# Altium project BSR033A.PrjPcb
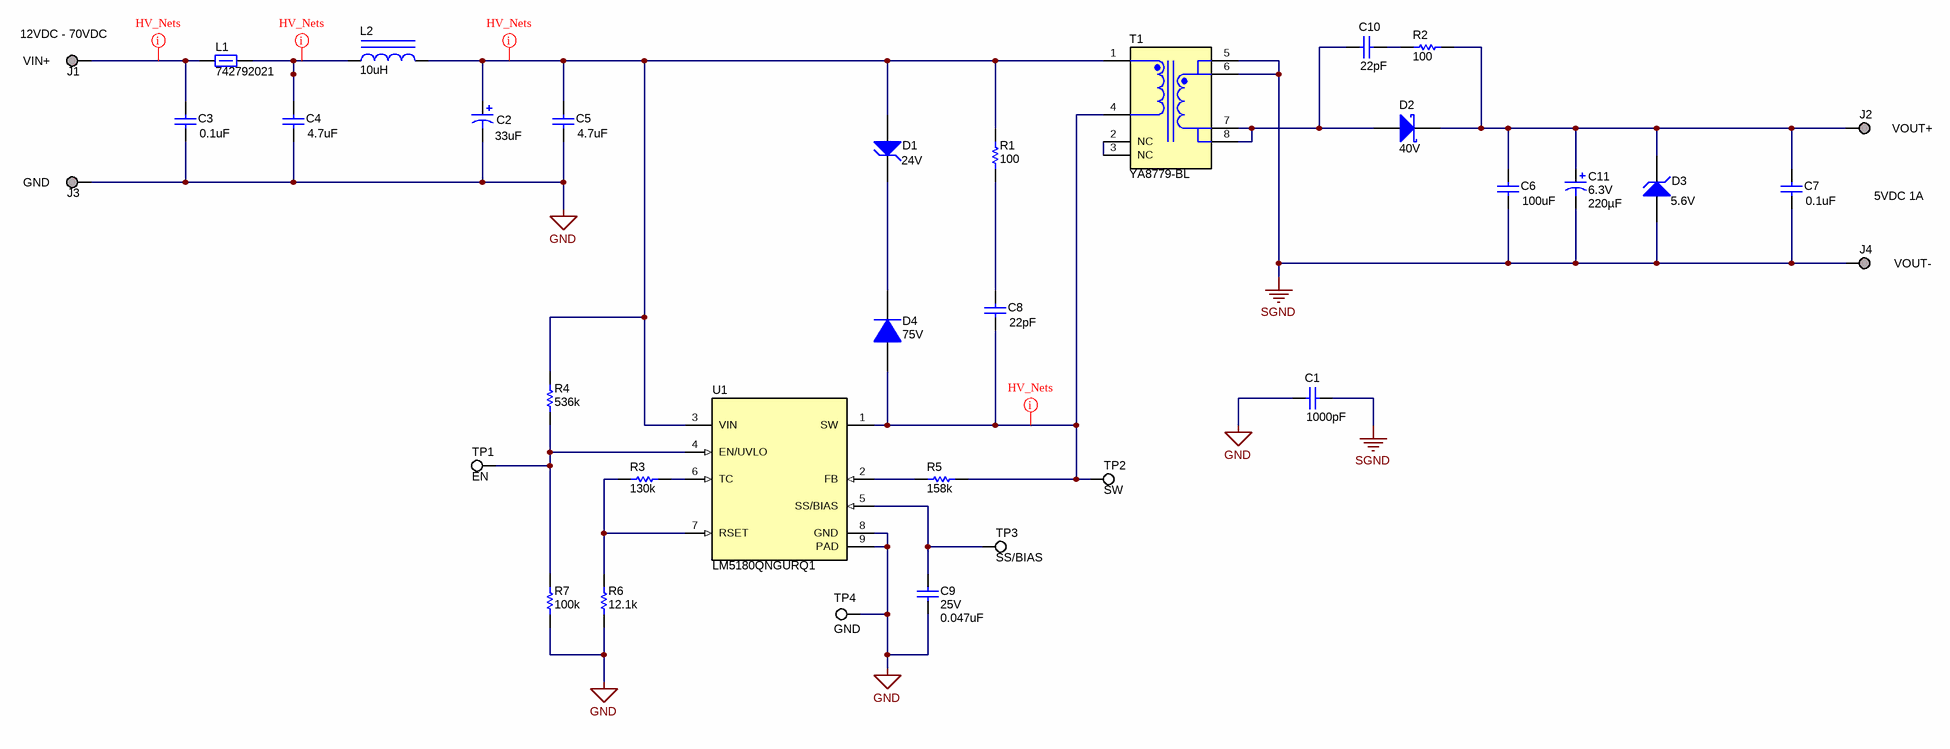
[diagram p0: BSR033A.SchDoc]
CopyrightYear: 2017; PCB_Layout: K Nielson; PCB_Rev: A; PRJ_Customer: Public Release; PRJ_Engineer: T Hegarty; PRJ_Number: BSR033; PRJ_Title: LM5180EVM-S05; SCH_Rev: A; TechSupport: http://www.ti.com/support; TID: N/A; VIN_Config: 18VDC - 70VDC; VOUT_ADC: 1A; VOUT_VDC: 5VDC
2 sheets, 53 parts. Net scope: global (net labels, ports and power ports of the same name join across sheets).
Board file: BSR033A.PcbDoc
Sheets:
  BSR033A.SchDoc
  BSR033A_Hardware.SchDoc

## Sheet BSR033A.SchDoc: LM5180EVM-S05 Buck Converter Schematic
size 431 x 279 mm; Date: Not shown in title block; ApprovedBy: Not shown in title block; CheckedBy: Not shown in title block; Author: Not shown in title block; CompanyName: Not shown in title block; DrawnBy: K Nielson; Engineer: Not shown in title block; Organization: Not shown in title block; Address1: Not shown in title block; Address2: Not shown in title block; Address3: Not shown in title block; Address4: Not shown in title block; DocumentNumber: 1; Revision: Use project parameter SCH_Rev; SheetNumber: 1; SheetTotal: 2; PageSetup: Record=PageOptions¦CenterHorizontal=True¦CenterVertical=True¦PrintScale=1.00¦XCorrection=1.00¦YCorrection=1.00¦PrintKind=0¦BorderSize=5000000¦LeftOffset=0¦BottomOffset=0¦Orientation=2¦PaperLength=1000¦PaperWidth=1000¦Scale=100¦PaperSource=15¦PrintQuality=600¦MediaType=1¦DitherType=10¦PaperKind=Letter¦PrintScaleMode=1

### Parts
C1  ValueDisplayed: 1000pF  [1206_190]  (hidden comment: 202R18W102KV4E)
C2  ValueDisplayed: 33uF  [SM_RADIAL_G]  (hidden comment: EEE-FK2A330P)
C3  ValueDisplayed: 0.1uF  [0603L]  (hidden comment: GRM188R72A104KA35J)
C4  ValueDisplayed: 4.7uF  [1210_220]  (hidden comment: GRM32DC72A475KE01L)
C5  ValueDisplayed: 4.7uF  [1210_220]  (hidden comment: GRM32DC72A475KE01L)
C6  ValueDisplayed: 100uF  [1210_270]  (hidden comment: GRM32EC80J107ME20L)
C7  ValueDisplayed: 0.1uF  [0603L]  (hidden comment: GRM188R72A104KA35J)
C8  ValueDisplayed: 22pF  [0603_HV]  (hidden comment: GRM1885C2A220JA01D)
C9  VDC_V: 25V  ValueDisplayed: 0.047uF  [0603L]  (hidden comment: GCM188R71E473KA37D)
C10  ValueDisplayed: 22pF  [0603_HV]  (hidden comment: GRM1885C2A220JA01D)
C11  VDC_V: 6.3V  ValueDisplayed: 220µF  [7343-31]  (hidden comment: T598D107M010ATE025)
D1  Vz_V: 24V  [PowerDI123]  (hidden comment: DFLZ24-7)
D2  40V  [SMAF]
D3  Vz_V: 5.6V  [SOD-323]  (hidden comment: MMSZ5232BS-7-F)
D4  75V  [SOD-323]
J1  1573-2  [Keystone1573-2]  (value not drawn)
J2  1573-2  [Keystone1573-2]  (value not drawn)
J3  1573-2  [Keystone1573-2]  (value not drawn)
J4  1573-2  [Keystone1573-2]  (value not drawn)
L1  742792021  [0805_HV]
L2  ValueDisplayed: 10uH  [WE-TPC-M1]  (hidden comment: 744042100)
R1  ValueDisplayed: 100  [0603L]  (hidden comment: CRCW0603100RFKEA)
R2  ValueDisplayed: 100  [0603L]  (hidden comment: CRCW0603100RFKEA)
R3  ValueDisplayed: 130k  [0603L]  (hidden comment: CRCW0603130KFKEA)
R4  ValueDisplayed: 536k  [0603_HV]  (hidden comment: CRCW0603536KFKEA)
R5  ValueDisplayed: 158k  [0603_HV]  (hidden comment: CRCW0603158KFKEA)
R6  ValueDisplayed: 12.1k  [0603L]  (hidden comment: CRCW060312K1FKEA)
R7  ValueDisplayed: 100k  [0603L]  (hidden comment: CRCW0603100KFKEA)
T1  YA8779-BL  [Coilcraft_YA8779-CL]
TP1  EN  [Testpoint_Keystone_Miniature]
TP2  SW  [Testpoint_Keystone_Miniature]
TP3  SS/BIAS  [Testpoint_Keystone_Miniature]
TP4  GND  [Testpoint_Keystone_Miniature]
U1  LM5180QNGURQ1  [NGU0008C]

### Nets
GND: C1.2 C2.2(-) C3.2 C4.1 C5.1 C9.2 J3.1 R6.1 R7.1 TP4.1 U1.8(GND) U1.9(PAD)
SGND: C1.1 C6.2 C7.2 C11.2(-) D3.2(A) J4.1 T1.5 T1.6
NetC2_1: C2.1(+) C5.2 D1.2(A) L2.2 R1.2 R4.2 T1.1 U1.3(VIN)
NetC3_1: C3.1 J1.1 L1.1
NetC4_2: C4.2 L1.2 L2.1
NetC6_1: C6.1 C7.1 C11.1(+) D2.1(K) D3.1(K) J2.1 R2.1
NetC8_1: C8.1 R1.1
NetC8_2: C8.2 D4.2(A) R5.2 T1.4 TP2.1 U1.1(SW)
NetC9_1: C9.1 TP3.1 U1.5(SS/BIAS)
NetC10_1: C10.1 R2.2
NetC10_2: C10.2 D2.2(A) T1.7 T1.8
NetD1_1: D1.1(K) D4.1(K)
NetR3_1: R3.1 R6.2 U1.7(RSET)
NetR3_2: R3.2 U1.6(TC)
NetR4_1: R4.1 R7.2 TP1.1 U1.4(EN/UVLO)
NetR5_1: R5.1 U1.2(FB)
NetT1_2: T1.2(NC) T1.3(NC)

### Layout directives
net class HV_Nets: NetC2_1, NetC3_1, NetC4_2, NetC8_2

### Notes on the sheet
- (near J1) 12VDC - 70VDC
- (near J1) VIN+
- (near J3) GND
- (near J2) VOUT+
- 5VDC 1A
- (near J4) VOUT-

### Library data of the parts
C1 = CMP-0008572-2: CAP, CERM, 1000 pF, 2000 V, +/- 10%, X7R, 1206_190; Manufacturer: Johanson Technology; TaMin_C: -55°C; Polarized: N; SizeAreaWB_mm2: 10.92; Value1: Unknown; U/M: EA; Value: 1000pF; TaMax_C: 125°C; SizeZ_mm: 1.9; SizeX_mm: 3.2; SizeY_mm: 1.6; Cap_Case: 1206; Value2: 2000V; SizeArea_mm2: 5.12; CompType: Capacitor; Cap_F: 1nF; VDC_V: 2kV; AEC Category: Q200
C2 = CMP-0011203-2: CAP, AL, 33 uF, 100 V, +/- 20%, 0.7 ohm, AEC-Q200 Grade 2, SMD; Manufacturer: Panasonic; TaMin_C: -55°C; Polarized: Y; SizeAreaWB_mm2: 172.2; Value1: 0.7 ohm; U/M: EA; Value: 33uF; TaMax_C: 105°C; SizeZ_mm: 10.2; SizeX_mm: 12; SizeY_mm: 10.3; Cap_Case: G; Value2: 100V; SizeArea_mm2: 123.6; CompType: Capacitor; Cap_F: 33µF; IRMS_A: 2dA; AEC Grade: 2; AEC Category: Q200; ESR_ohm: 7d
C3 C7 = CMP-0007470-5: CAP, CERM, 0.1 uF, 100 V, +/- 10%, X7R, 0603; Manufacturer: MuRata; TaMin_C: -55°C; Polarized: N; SizeAreaWB_mm2: 4.68; Value1: Unknown; U/M: EA; Value: 0.1uF; TaMax_C: 125°C; SizeZ_mm: 1; SizeX_mm: 1.6; SizeY_mm: 0.8; Cap_Case: 0603; Value2: 100V; SizeArea_mm2: 1.28; CompType: Capacitor; Cap_F: 100nF; AEC Category: Q200
C4 C5 = CMP-0009182-2: CAP, CERM, 4.7 uF, 100 V, +/- 10%, X7S, 1210; Manufacturer: MuRata; TaMin_C: -55°C; Polarized: N; SizeAreaWB_mm2: 14.7; Value1: Unknown; U/M: EA; Value: 4.7uF; TaMax_C: 125°C; SizeZ_mm: 2.2; SizeX_mm: 3.2; SizeY_mm: 2.5; Cap_Case: 1210; Value2: 100V; SizeArea_mm2: 8; CompType: Capacitor; Cap_F: 4.7µF; AEC Category: Q200
C6 = CMP-0009199-2: CAP, CERM, 100 uF, 6.3 V, +/- 20%, X6S, 1210; Manufacturer: MuRata; TaMin_C: -55°C; Polarized: N; SizeAreaWB_mm2: 14.7; Value1: Unknown; U/M: EA; Value: 100uF; TaMax_C: 105°C; SizeZ_mm: 2.7; SizeX_mm: 3.2; SizeY_mm: 2.5; Cap_Case: 1210; Value2: 6.3V; SizeArea_mm2: 8; Cap_F: 100µF; AEC Category: Q200
C8 = CMP-0007255-4: CAP, CERM, 22 pF, 100 V, +/- 5%, C0G/NP0, 0603; Manufacturer: MuRata; TaMin_C: -55°C; Polarized: N; SizeAreaWB_mm2: 4.68; Value1: Unknown; U/M: EA; Value: 22pF; TaMax_C: 125°C; SizeZ_mm: 1; SizeX_mm: 1.6; SizeY_mm: 0.8; Cap_Case: 0603; Value2: 100V; SizeArea_mm2: 1.28; CompType: Capacitor; AEC Category: Q200
C9 = CMP-0007141-5: CAP, CERM, 0.047 uF, 25 V, +/- 10%, X7R, AEC-Q200 Grade 1, 0603; Manufacturer: MuRata; TaMin_C: -55°C; Polarized: N; SizeAreaWB_mm2: 4.68; Value1: Unknown; U/M: EA; TaMax_C: 125°C; SizeZ_mm: 1; SizeX_mm: 1.6; SizeY_mm: 0.8; Cap_Case: 0603; SizeArea_mm2: 1.28; CompType: Capacitor; AEC Qualified: Y; Cap_F: 47nF; AEC Category: Q200
C10 = CMP-0007255-4: CAP, CERM, 22 pF, 100 V, +/- 5%, C0G/NP0, 0603; Manufacturer: MuRata; TaMin_C: -55°C; Polarized: N; SizeAreaWB_mm2: 4.68; U/M: EA; Value: 22pF; TaMax_C: 125°C; SizeZ_mm: 1; SizeX_mm: 1.6; SizeY_mm: 0.8; Cap_Case: 0603; Value2: 100V; SizeArea_mm2: 1.28; CompType: Capacitor; AEC Category: Q200; Value1: Unknown
C11 = CMP-0074683-2: CAP, Aluminum Polymer, 220 µF, 6.3 V,+/- 20%, 0.01 ohm, 7343-31 SMD; Manufacturer: MuRata; PartNumber: ECASD60J227M010K00; TaMin_C: -40°C; ESR_ohm: 0.01; Polarized: Y; SizeAreaWB_mm2: 58.59; Value: 220uF; TaMax_C: 105°C; SizeZ_mm: 3.1; SizeX_mm: 7.3; SizeY_mm: 4.3; SizeArea_mm2: 31.39; CompType: Capacitor; AEC Qualified: N; IRMS_A: 3A; AEC Category: Q200
D1 = CMP-0005415-2: Diode, Zener, 24 V, 1 W, PowerDI123; Manufacturer: Diodes Inc.; Power_W: 1W; SizeAreaWB_mm2: 13.066; RJA_CperW: 110; U/M: EA; Value: 24V; SizeZ_mm: 0.98; SizeX_mm: 3.7; SizeY_mm: 1.78; SizeArea_mm2: 6.586; AEC Category: Q101
D2 = CMP-0028855-1: Diode, Schottky, 40 V, 3 A, AEC-Q101, SMAF; PartNumber: FSV340AF; Manufacturer: Fairchild Semiconductor; SizeAreaWB_mm2: 19.95; SizeArea_mm2: 11.75; AEC Qualified: Y; TJmax_C: 150°C; AEC Category: Q101; SizeZ_mm: 1; Green_REACh: Incomplete; Io_A: 3A; Vf_V: 5dV; SizeY_mm: 2.5; Value2: 0.5V; Green_Lifecycle: Not Set; U/M: EA; SizeX_mm: 4.7
D3 = CMP-0005855-1: Diode, Zener, 5.6 V, 200 mW, SOD-323; Manufacturer: Diodes Inc.; Power_W: 200mW; SizeAreaWB_mm2: 8.695; Value1: 0.2W; RJA_CperW: 350; U/M: EA; Value: 5.6V; SizeZ_mm: 1; SizeX_mm: 2.7; SizeY_mm: 1.35; SizeArea_mm2: 3.645; AEC Category: Q101
D4 = CMP-0029019-1: Diode, Ultrafast, 75 V, 0.25 A, SOD-323; Manufacturer: Central Semiconductor; PartNumber: CMDD4448; Io_A: 2.5dA; Green_Lifecycle: Not Set; SizeAreaWB_mm2: 8.695; Green_REACh: Incomplete; Value1: 0.25A; TJmax_C: 175°C; U/M: EA; SizeZ_mm: 1; SizeX_mm: 2.7; SizeY_mm: 1.35; Vf_V: 1.2V; SizeArea_mm2: 3.645; AEC Category: Q101
J1-J4 = CMP-0055119-1: Terminal, Turret, TH, Double; Manufacturer: Keystone; CT: FALSE; Green_REACh: Passed; CompType: Turret Terminal; Green_Lifecycle: Active
L1 = CMP-0003072-1: Ferrite Bead, 22 ohm @ 100 MHz, 6 A, 0805; Manufacturer: Wurth Elektronik; Ztyp@1GHz_Ohm: 40.219; ZTyp@100MHz_Ohm: 22; SizeAreaWB_mm2: 6.75; DCR_ohm: 8m; Value1: 0.008 ohm; Value: 22 ohm; Imax_A: 6A; SizeZ_mm: 1.45; SizeX_mm: 2; SizeY_mm: 1.25; SizeArea_mm2: 2.5
L2 = CMP-0063804-1: Inductor, Shielded Drum Core, Ferrite, 10 uH, 1 A, 0.12 ohm, SMD; Manufacturer: Wurth Elektronik; Isat: 1A @ 35% inductance drop; Irms: 1.3A @ 30C rise; Green_Lifecycle: Active; SizeAreaWB_mm2: 33.64; DCR_ohm: 1.2d; Green_REACh: Passed; Value: 10uH; Imax_A: 1A; SizeZ_mm: 1.8; SizeX_mm: 4.8; SizeArea_mm2: 23.04; Ind_H: 10µH; AEC Category: Q200
R1 R2 = CMP-0021991-3: RES, 100, 1%, 0.1 W, 0603; Manufacturer: Vishay-Dale; Power_W: 100mW; TempCo: 100 ppm/C; Value_Code: 100R; U/M: EA; Value: 100; EIA_Code: E96; SizeX_mm: 1.6; SizeY_mm: 0.8; SizeZ_mm: 1; Value2: 0.1W; SizeArea_mm2: 1.28; CompType: Resistor; VDC_V: 75V; AEC Category: Q200
R3 = CMP-0022036-4: RES, 130 k, 1%, 0.1 W, AEC-Q200 Grade 0, 0603; Manufacturer: Vishay-Dale; Power_W: 100mW; TempCo: 100 ppm/C; Value: 130k; EIA_Code: E96; SizeX_mm: 1.6; SizeY_mm: 0.8; SizeZ_mm: 1; Value2: 0.1W; SizeArea_mm2: 1.28; CompType: Resistor; AEC Qualified: Y; VDC_V: 75V; AEC Category: Q200; AEC Grade: 0
R4 = CMP-0022488-4: RES, 536 k, 1%, 0.1 W, AEC-Q200 Grade 0, 0603; Manufacturer: Vishay-Dale; Power_W: 100mW; TempCo: 100 ppm/C; Value: 536k; EIA_Code: E96; SizeX_mm: 1.6; SizeY_mm: 0.8; SizeZ_mm: 1; Value2: 0.1W; SizeArea_mm2: 1.28; CompType: Resistor; AEC Qualified: Y; VDC_V: 75V; AEC Category: Q200; AEC Grade: 0
R5 = CMP-0022064-4: RES, 158 k, 1%, 0.1 W, AEC-Q200 Grade 0, 0603; Manufacturer: Vishay-Dale; Power_W: 100mW; TempCo: 100 ppm/C; Value: 158k; EIA_Code: E96; SizeX_mm: 1.6; SizeY_mm: 0.8; SizeZ_mm: 1; Value2: 0.1W; SizeArea_mm2: 1.28; CompType: Resistor; AEC Qualified: Y; VDC_V: 75V; AEC Category: Q200; AEC Grade: 0
R6 = CMP-0022030-3: RES, 12.1 k, 1%, 0.1 W, 0603; Manufacturer: Vishay-Dale; Power_W: 100mW; TempCo: 100 ppm/C; Value_Code: 12k1; U/M: EA; Value: 12.1k; EIA_Code: E96; SizeX_mm: 1.6; SizeY_mm: 0.8; SizeZ_mm: 1; Value2: 0.1W; SizeArea_mm2: 1.28; CompType: Resistor; VDC_V: 75V; AEC Category: Q200
R7 = CMP-0021990-4: RES, 100 k, 1%, 0.1 W, AEC-Q200 Grade 0, 0603; Manufacturer: Vishay-Dale; Power_W: 100mW; TempCo: 100 ppm/C; Value: 100k; EIA_Code: E96; SizeX_mm: 1.6; SizeY_mm: 0.8; SizeZ_mm: 1; Value2: 0.1W; SizeArea_mm2: 1.28; CompType: Resistor; AEC Qualified: Y; VDC_V: 75V; AEC Category: Q200; AEC Grade: 0
T1 = CMP-0085524-1: Transformer, 30 uH, SMD; Manufacturer: Coilcraft; SizeAreaWB_mm2: 137.86; SizeArea_mm2: 94.86; AEC Qualified: N; Lp: 30; AEC Category: Q200; Value: 30uH; SizeZ_mm: 10.6; Ind_H: 30µH; SizeY_mm: 10.2; Ns1toNp: 0.33; Rsec1_ohm: 0.025; DCR_ohm: 0.014; SizeX_mm: 9.3; LeakageInd_H: 380nH
TP1-TP4 = CMP-0055152-1: Test Point, Miniature, SMT; Manufacturer: Keystone; PartNumber: 5015; CNHeader: FALSE; Green_Lifecycle: Active; Green_REACh: Passed; CT: TRUE
U1 = CMP-0078633-2: 70-V PSR Flyback Converter With 100-V, 1.2-A Power Switch and Ultra-Low IQ, NGU0008C (WSON-8); Alternate PartNumber: LM5180QNGUTQ1; Alternate Manufacturer: Texas Instruments; Alternate Manufacturer: None; SizeAreaWB_mm2: 25; SizeZ_mm: 0.8; SizeX_mm: 4; SizeArea_mm2: 16; CompType: IC; AEC Qualified: Y; AEC Category: Q200

## Sheet BSR033A_Hardware.SchDoc: LM5180EVM-S03 Buck Converter Hardware
size 431 x 279 mm; Date: Not shown in title block; ApprovedBy: Not shown in title block; CheckedBy: Not shown in title block; Author: Not shown in title block; CompanyName: Not shown in title block; DrawnBy: K. Nielson; Engineer: Not shown in title block; Organization: Not shown in title block; Address1: Not shown in title block; Address2: Not shown in title block; Address3: Not shown in title block; Address4: Not shown in title block; DocumentNumber: 2; Revision: Use project parameter SCH_Rev; SheetNumber: 2; SheetTotal: 2; PageSetup: Record=PageOptions¦CenterHorizontal=True¦CenterVertical=True¦PrintScale=1.00¦XCorrection=1.00¦YCorrection=1.00¦PrintKind=0¦BorderSize=5000000¦LeftOffset=0¦BottomOffset=0¦Orientation=2¦PaperLength=1000¦PaperWidth=1000¦Scale=100¦PaperSource=15¦PrintQuality=600¦MediaType=1¦DitherType=10¦PaperKind=Letter¦PrintScaleMode=1
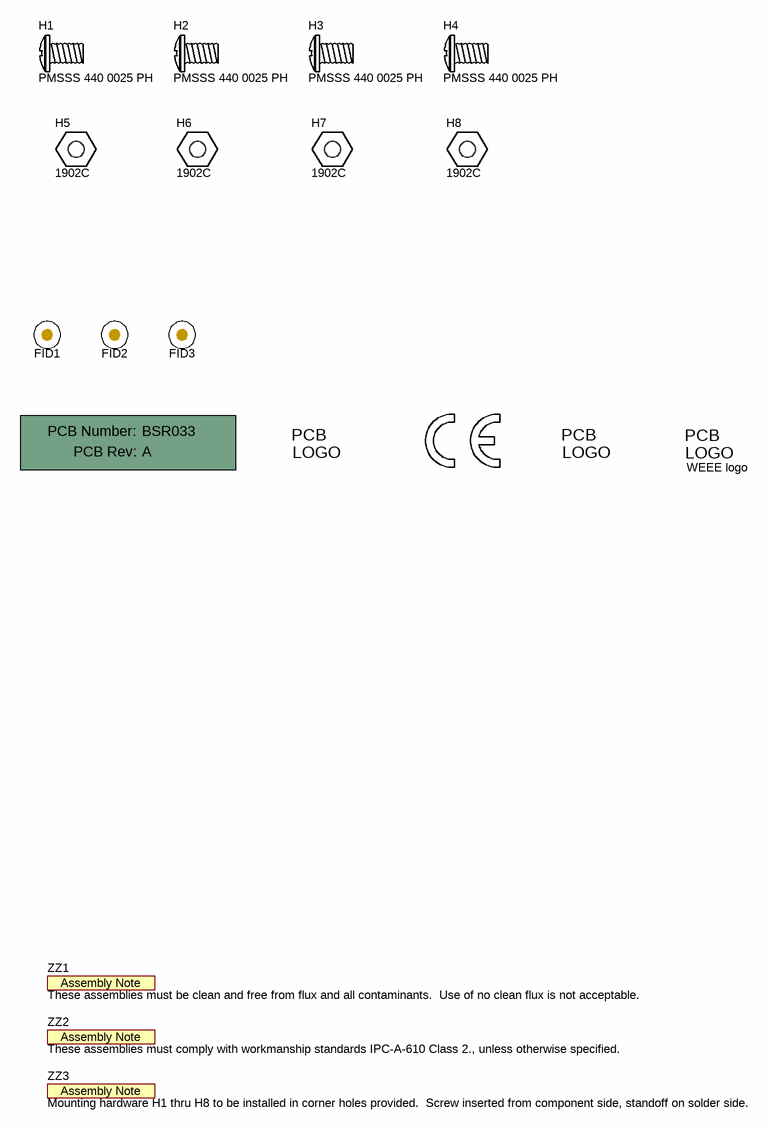
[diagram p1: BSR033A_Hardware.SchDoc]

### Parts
!PCB  Printed Circuit Board  (value not drawn)  (mechanical)
FID1  Fiducial  [Fiducial10-20]  (value not drawn)
FID2  Fiducial  [Fiducial10-20]  (value not drawn)
FID3  Fiducial  [Fiducial10-20]  (value not drawn)
H1  PMSSS 440 0025 PH  [B_F_PMSSS4400025PH]
H2  PMSSS 440 0025 PH  [B_F_PMSSS4400025PH]
H3  PMSSS 440 0025 PH  [B_F_PMSSS4400025PH]
H4  PMSSS 440 0025 PH  [B_F_PMSSS4400025PH]
H5  1902C  [Keystone_1902C]
H6  1902C  [Keystone_1902C]
H7  1902C  [Keystone_1902C]
H8  1902C  [Keystone_1902C]
Logo1  Texas Instruments  [TI_Stacked_Overlay_Small]  (value not drawn)  (no BOM)
Logo2  WEEE logo  [WEEE_Minimum]  (no BOM)
Logo3  FCC disclaimer  [FCC_disclaimer_stacked]  (value not drawn)  (no BOM)
LOGO4  CE Mark  [CE_Mark_5mm]  (value not drawn)  (no BOM)
ZZ1  These assemblies must be clean and free from flux and all contaminants.  Use of no clean flux is not acceptable.  [AssemblyNote]  (no BOM)
ZZ2  These assemblies must comply with workmanship standards IPC-A-610 Class 2., unless otherwise specified.  [AssemblyNote]  (no BOM)
ZZ3  Mounting hardware H1 thru H8 to be installed in corner holes provided.  Screw inserted from component side, standoff on solder side.  [AssemblyNote]  (no BOM)

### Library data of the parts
!PCB = PCB: Manufacturer: Any; PartNumber: BSR033; SymbolCreator: a0412235
FID1-FID3 = Fiducial: Fiducial mark.  There is nothing to buy or mount.; SymbolCreator: codlsc
H1 H2 H4 = CMP-0003715-1: MACHINE SCREW PAN PHILLIPS 4-40; Manufacturer: B&F Fastener Supply; CompType: Standoff; Component Classes: MountingHoles
H3 = CMP-0003715-1: MACHINE SCREW PAN PHILLIPS 4-40; Manufacturer: B&F Fastener Supply; CompType: Standoff; Component Classes: MountingHoles; Rule: PcbType=ProtelPcb
H5-H8 = CMP-0003610-1: Standoff, Hex, 0.5"L #4-40 Nylon; Manufacturer: Keystone; CompType: Hardware; Component Classes: MountingHoles
Logo1 = TI_Logo: Texas Instrument Corporate Signature; SymbolCreator: a0412235
Logo2 = CMP-0074769-1
Logo3 = FCC_disclaimer: SymbolCreator: a0412235
LOGO4 = CE Mark: SymbolCreator: a0412235
ZZ1-ZZ3 = AssemblyNote: SymbolCreator: codlsc

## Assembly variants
001: not fitted C11 FID1 FID2 FID3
